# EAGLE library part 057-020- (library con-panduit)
CONNECTOR 20-pin series 057 contact pc board low profile headers
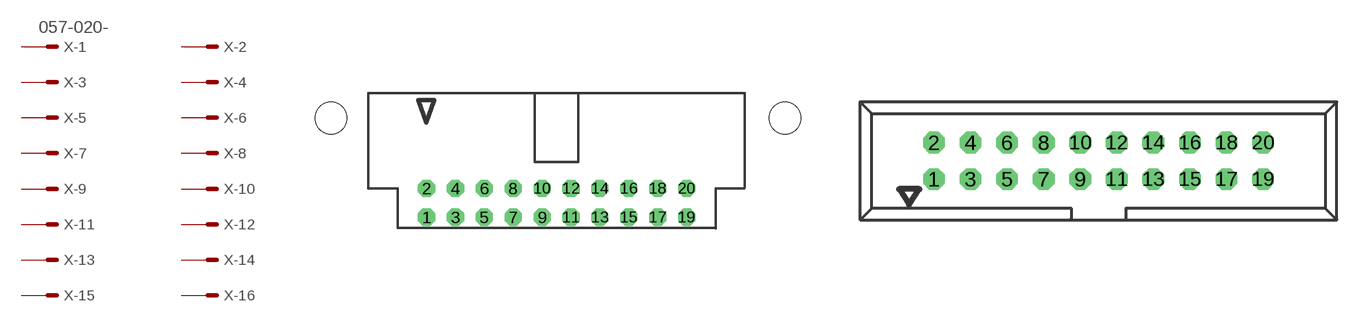
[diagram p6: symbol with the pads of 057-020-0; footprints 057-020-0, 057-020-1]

Designator prefix X; gates -1=MV -2=M -3=M -4=M -5=M -6=M -7=M -8=M -9=M -10=M -11=M -12=M -13=M -14=M -15=M -16=M -17=M -18=M -19=M -20=M

## 057-020-0 (OC_FARNELL: unknown; OC_NEWARK: unknown)  [057-020-0]
1  -1:S  pas
2  -2:S  pas
3  -3:S  pas
4  -4:S  pas
5  -5:S  pas
6  -6:S  pas
7  -7:S  pas
8  -8:S  pas
9  -9:S  pas
10  -10:S  pas
11  -11:S  pas
12  -12:S  pas
13  -13:S  pas
14  -14:S  pas
15  -15:S  pas
16  -16:S  pas
17  -17:S  pas
18  -18:S  pas
19  -19:S  pas
20  -20:S  pas

## 057-020-1 (OC_FARNELL: unknown; OC_NEWARK: unknown)  [057-020-1]
Pads as for 057-020-0

## Footprint 057-020-0 (pad centres in mm)
CONNECTOR series 057 contact pc board low profile headers angled
drill 1 octagon: 1 -11.43,-5.08; 2 -11.43,-2.54; 3 -8.89,-5.08; 4 -8.89,-2.54; 5 -6.35,-5.08; 6 -6.35,-2.54; 7 -3.81,-5.08; 8 -3.81,-2.54; 9 -1.27,-5.08; 10 -1.27,-2.54; 11 1.27,-5.08; 12 1.27,-2.54; 13 3.81,-5.08; 14 3.81,-2.54; 15 6.35,-5.08; 16 6.35,-2.54; 17 8.89,-5.08; 18 8.89,-2.54; 19 11.43,-5.08; 20 11.43,-2.54
hole 2.8 at -19.83,3.66
hole 2.8 at 20.08,3.66

## Footprint 057-020-1 (pad centres in mm)
CONNECTOR series 057 contact pc board low profile headers straight
drill 1 octagon: 1 -11.43,-1.27; 2 -11.43,1.27; 3 -8.89,-1.27; 4 -8.89,1.27; 5 -6.35,-1.27; 6 -6.35,1.27; 7 -3.81,-1.27; 8 -3.81,1.27; 9 -1.27,-1.27; 10 -1.27,1.27; 11 1.27,-1.27; 12 1.27,1.27; 13 3.81,-1.27; 14 3.81,1.27; 15 6.35,-1.27; 16 6.35,1.27; 17 8.89,-1.27; 18 8.89,1.27; 19 11.43,-1.27; 20 11.43,1.27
